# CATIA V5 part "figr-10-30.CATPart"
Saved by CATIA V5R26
Part number: Part1
Bounding box of the stored display mesh (mm): x -72 to 28.909, y -84.823 to 54.826, z -29.324 to 42.024
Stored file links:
  D:\_Deepak\CATIA\CATIA V5-6R2016_Deepak\Resources\Part files\Partfiles\c10_catia_v5_6r2016_prt\figr-10-30.CATPart
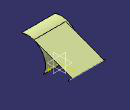
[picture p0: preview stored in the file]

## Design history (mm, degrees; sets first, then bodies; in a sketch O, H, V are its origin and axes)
Body1 (main body)
  Sketch1 on yz-plane, origin (0, 0, 0), H (0, 1, 0), V (0, 0, 1)
    arc A1 centre (-67.861, -7.2287) radius 49.2558 from (-84.8225, 39.0145) to (-23.8391, -29.3242) cw
  Extrude1: Element1 Sketch1, Lim1 20, Lim2 72
  Sketch2 on xy-plane, origin (0, 0, 0), H (1, 0, 0), V (0, 1, 0)
    line L1 (-67.3145, 54.8256) -> (28.9089, 54.8256)
    horizontal: L1 H
  Sweep1: type Segment, GuideCrv Sketch2, GuideSurf Extrude1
